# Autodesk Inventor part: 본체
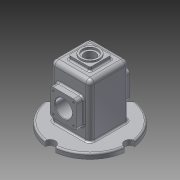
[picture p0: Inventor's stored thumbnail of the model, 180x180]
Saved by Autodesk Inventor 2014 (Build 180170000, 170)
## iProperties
Created: 2018-07
Part Number: 본체
Material: 알루미늄 6061
Document SubType Name: Modeling
Designer: OA65
Density: 2.71 g/cm^3
Appearance: 알루미늄 - 평지
Mass: 912.794 g
Surface Area: 1017.53 cm^2
Volume: 336.824 cm^3
Author: OA65
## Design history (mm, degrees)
sketch "스케치1"
  geometry: L1 (37, -37)-(-37, -37); L2 (-37, -37)-(-37, 37); L3 (-37, 37)-(37, 37); L4 (37, 37)-(37, -37); L5 (37, -37)-(-37, 37); L6 (-37, -37)-(37, 37); 1 further point
  constraints: 12 end point, 2 midpoint, 2 parallel, 1 horizontal, 1 perpendicular
  dimensions: "d0" = 74 distance of L2.end L3.end; "d1" = 74 distance of L1.end L2.end
extrude "돌출1" new body sketch "스케치1" distance "d2" = 110; taper "d3" = 0 deg
fillet "모깎기1" dims "d4" = 8
feature "쉘1" dims "d5" = 5
sketch "스케치2"
  geometry: L1 (58, 0)-(0, 0) reference; L2 (4, 80)-(54, 80); L3 (54, 80)-(54, 30); L4 (54, 30)-(4, 30); L5 (4, 30)-(4, 80); L6 (4, 80)-(54, 30); L7 (54, 80)-(4, 30); L8 (66, 0)-(58, 0) reference; 4 further points
  constraints: 12 end point, 4 midpoint, 2 parallel, 1 horizontal, 1 perpendicular, 1 vertical alignment
  dimensions: "d6" = 50 distance of L3.end L4.end; "d7" = 50 distance of L2.end L3.end; "d8" = 55 distance from line of point (29, 55) L8
extrude "돌출2" join sketch "스케치2" distance "d9" = 13; taper "d10" = 0 deg
sketch "스케치3"
  geometry: L1 (58, -102)-(0, -102) reference; L2 (4, -22)-(54, -22) reference; L3 (54, -22)-(54, -72) reference; L4 (54, -72)-(4, -72) reference; L5 (4, -72)-(4, -22) reference; L6 (4, -72)-(54, -72) reference; C1 r 25 at (29, -47); 2 further points
  constraints: 1 centre point, 1 midpoint, 1 vertical alignment
  dimensions: "d11" = 50 diameter of C1; "d12" = 55 distance from line of C1.centre L1
extrude "돌출3" join sketch "스케치3" distance "d13" = 7; taper "d14" = -20 deg
sketch "스케치4"
  geometry: L1 (54, 80)-(4, 80) reference; L2 (4, 80)-(4, 30) reference; L3 (4, 30)-(54, 30) reference; L4 (54, 30)-(54, 80) reference; L5 (58, 0)-(0, 0) reference; C1 r 16 at (29, 55); 1 further point
  constraints: 1 centre point, 1 vertical alignment
  dimensions: "d15" = 32 diameter of C1; "d16" = 55 distance from line of C1.centre L5
extrude "돌출4" cut sketch "스케치4" stored distance "d17" = 7; taper "d18" = 0 deg
fillet "모깎기2" dims "d19" = 6
fillet "모깎기3" dims "d20" = 3
fillet "모깎기4" dims "d21" = 3
sketch "스케치5"
  geometry: A1 r 6 centre (10, 74) between (10, 80) and (4, 74) reference; A2 r 6 centre (10, 36) between (4, 36) and (10, 30) reference; A3 r 6 centre (48, 36) between (48, 30) and (54, 36) reference; A4 r 6 centre (48, 74) between (54, 74) and (48, 80) reference; 5 further points
  constraints: 4 coincident
hole "구멍1" sketch "스케치5" at (10, 74), (10, 36), (48, 36), (48, 74) diameter "d22" = 3.242; stored, may be unused: countersink angle "d26" = 90 deg, drill point angle "d28" = 118 deg; dims "d23" = 8, "d24" = 4, "d25" = 2, "d27" = 10
sketch "스케치6"
  geometry: L1 (-37, 29)-(-37, -29) reference; L2 (-29, -37)-(29, -37) reference; L3 (37, -29)-(37, 29) reference; L4 (29, 37)-(-29, 37) reference; L5 (29, -32)-(-29, -32) reference; L6 (-32, -29)-(-32, 29) reference; L7 (-29, 32)-(29, 32) reference; L8 (32, 29)-(32, -29) reference; L9 (-37, 29)-(-37, -29) reference; L10 (-29, -37)-(29, -37) reference; L11 (37, -29)-(37, 29) reference; L12 (29, 37)-(-29, 37) reference; C1 r 75 at (0, 0); A1 r 8 centre (-29, 29) between (-29, 37) and (-37, 29) reference; A2 r 8 centre (-29, -29) between (-37, -29) and (-29, -37) reference; A3 r 8 centre (29, -29) between (29, -37) and (37, -29) reference; A4 r 8 centre (29, 29) between (37, 29) and (29, 37) reference; A5 r 3 centre (29, -29) between (29, -32) and (32, -29) reference; A6 r 3 centre (-29, -29) between (-32, -29) and (-29, -32) reference; A7 r 3 centre (-29, 29) between (-29, 32) and (-32, 29) reference; A8 r 3 centre (29, 29) between (32, 29) and (29, 32) reference; A9 r 8 centre (-29, 29) between (-29, 37) and (-37, 29) reference; A10 r 8 centre (-29, -29) between (-37, -29) and (-29, -37) reference; A11 r 8 centre (29, -29) between (29, -37) and (37, -29) reference; A12 r 8 centre (29, 29) between (37, 29) and (29, 37) reference; 1 further point
  constraints: 1 centre point, 1 coincident
  dimensions: "d29" = 150 diameter of C1
extrude "돌출5" join sketch "스케치6" distance "d30" = 10; taper "d31" = 0 deg
sketch "스케치7"
  geometry: A1 r 75 centre (0, 0) between (0, 75) and (75, 0) reference; 2 further points
  constraints: 4 point on circle
hole "구멍2" sketch "스케치7" at (0, 75), (75, 0), (0, -75), (-75, 0) diameter "d32" = 20; stored, may be unused: countersink angle "d36" = 90 deg, drill point angle "d38" = 118 deg; dims "d33" = 8, "d34" = 4, "d35" = 2, "d37" = 10
sketch "스케치8"
  geometry: L1 (-20, -20)-(20, -20); L2 (20, -20)-(20, 20); L3 (20, 20)-(-20, 20); L4 (-20, 20)-(-20, -20); L5 (-20, -20)-(20, 20); L6 (20, -20)-(-20, 20); 1 further point
  constraints: 12 end point, 2 midpoint, 2 parallel, 1 horizontal, 1 perpendicular
  dimensions: "d40" = 40 distance of L3.end L2.end; "d41" = 40 distance of L2.end L1.end
extrude "돌출6" join sketch "스케치8" distance "d42" = 7; taper "d43" = 0 deg
sketch "스케치9"
  geometry: C1 r 17.5 at (0, 0); 1 further point
  constraints: 1 centre point, 1 coincident
  dimensions: "d44" = 35 diameter of C1
extrude "돌출7" join sketch "스케치9" distance "d45" = 3; taper "d46" = 0 deg
sketch "스케치10"
  geometry: C1 r 17.5 at (0, 0) reference; 1 further point
  constraints: 1 coincident
hole "구멍3" sketch "스케치10" at (0, 0) diameter "d47" = 21; stored, may be unused: countersink angle "d51" = 90 deg, drill point angle "d53" = 118 deg; dims "d48" = 8, "d49" = 28, "d50" = 4, "d52" = 30
sketch "스케치11"
  geometry: L1 (46.5, 18)-(11.5, 18) reference; L2 (66, -92)-(66, 0) reference; 2 further points
  constraints: 1 other
  dimensions: "d54" = 30 distance from line of point (29, -12) L1; "d55" = 37 distance from line of point (29, -12) L2
feature "엠보싱1" sketch "스케치11" dims "d0" = 74, "d1" = 74, "d6" = 50, "d7" = 50, "d8" = 55, "d56" = 0.5, "d57" = 0
fillet "모깎기6" dims "d58" = 3
fillet "모깎기7" dims "d59" = 3
chamfer "모따기1" distance "d60" = 1; stored, may be unused: second distance "d61" = 2, angle "d62" = 45 deg
node "솔리드1"
mirror "대칭1"
mirror "대칭2"
node "투영된 루프1"
node "투영된 루프2"
node "작업 평면1"
node "투영된 루프3"
